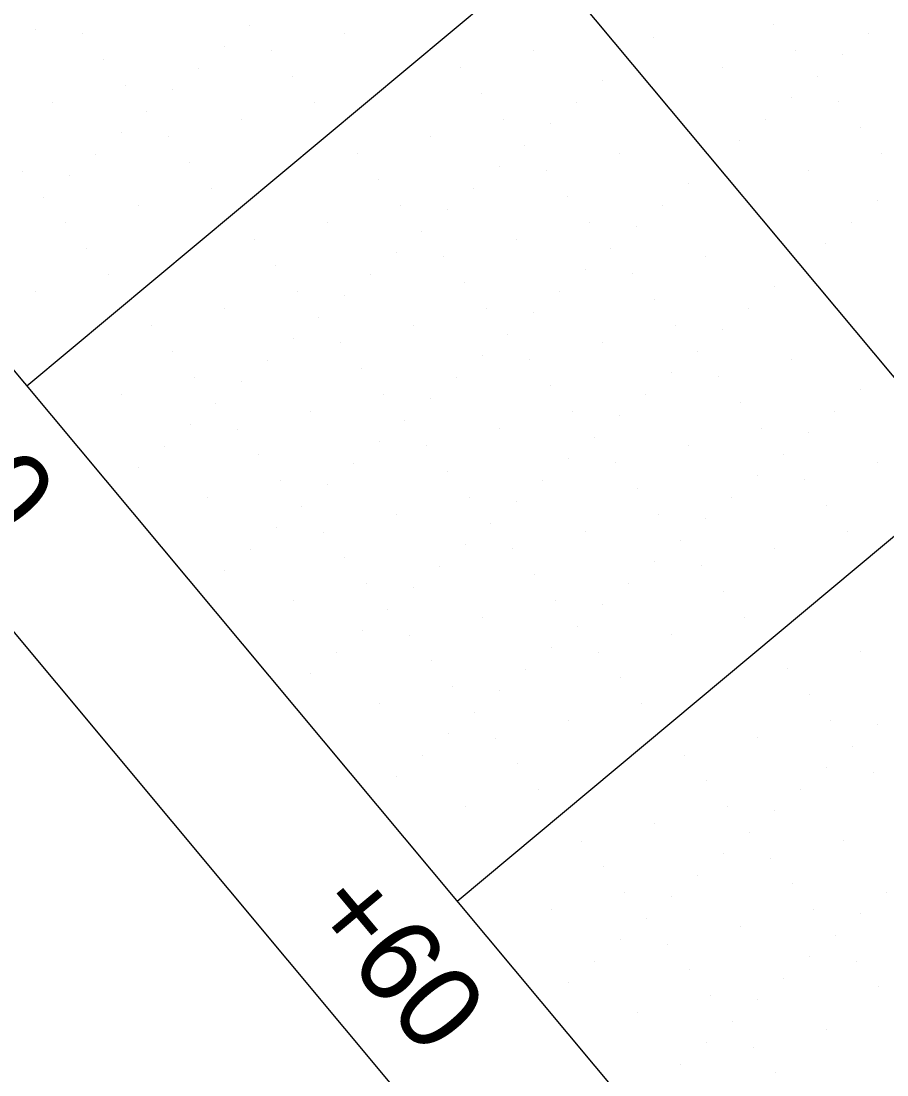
# Model space of a CAD drawing. Extents: x 2042995 to 2043795, y 305365 to 306249.
# Drawn here: x 2043194.69 to 2043220.5, y 305730.9 to 305762.3 of the extents above; entities that cross this region are included whole.
import ezdxf

# ---------------------------------------------------------------- set-up
doc = ezdxf.new("R2010")
doc.units = 0
for name, color, linetype in [('BR_BORDER LINES', 7, 'Continuous'), ('BR_CONCRETE', 7, 'Continuous'), ('BR_GRID DOTS', 7, 'Continuous'), ('BR_GRID LINES', 7, 'Continuous'), ('BR_TEXT', 7, 'Continuous')]:
    doc.layers.add(name, color=color, linetype=linetype)

msp = doc.modelspace()

# ---------------------------------------------------------------- linework, layer by layer
at = {"layer": 'BR_BORDER LINES'}
for p, q in [((2043026.498, 305945.211), (2043458.121, 305428.416)), ((2043041.019, 305935.624), (2043355.122, 305559.54))]:
    msp.add_line(p, q, dxfattribs=at)
at = {"layer": 'BR_CONCRETE'}
msp.add_spline([(2043139.109, 306017.548), (2043148.199, 306007.16), (2043160.233, 305993.368), (2043172.245, 305979.557), (2043184.234, 305965.727), (2043196.201, 305951.879), (2043208.145, 305938.012), (2043220.067, 305924.126), (2043231.966, 305910.221), (2043243.843, 305896.297), (2043255.698, 305882.355), (2043267.529, 305868.394), (2043279.339, 305854.414), (2043291.126, 305840.415), (2043302.89, 305826.398), (2043314.632, 305812.361), (2043326.352, 305798.306), (2043338.049, 305784.233), (2043349.724, 305770.14), (2043361.376, 305756.029), (2043373.005, 305741.899), (2043384.613, 305727.75), (2043396.197, 305713.582), (2043407.76, 305699.396), (2043419.299, 305685.191), (2043430.817, 305670.967), (2043442.311, 305656.724), (2043453.784, 305642.463), (2043465.234, 305628.182), (2043476.661, 305613.883), (2043488.066, 305599.566), (2043499.448, 305585.229), (2043510.808, 305570.874), (2043522.146, 305556.5), (2043533.461, 305542.107), (2043544.753, 305527.695), (2043547.219, 305524.543)], degree=3, dxfattribs=at)
at = {"layer": 'BR_GRID DOTS'}
for p, q in [((2043201.511, 305762.182), (2043201.511, 305762.182)), ((2043217.132, 305762.199), (2043217.132, 305762.199)), ((2043195.11, 305762.047), (2043195.11, 305762.047)), ((2043196.518, 305761.92), (2043196.518, 305761.92)), ((2043204.328, 305761.929), (2043204.328, 305761.929)), ((2043213.547, 305761.811), (2043213.547, 305761.811)), ((2043219.949, 305761.946), (2043219.949, 305761.946)), ((2043200.744, 305761.541), (2043200.744, 305761.541)), ((2043202.152, 305761.414), (2043202.152, 305761.414)), ((2043209.963, 305761.423), (2043209.963, 305761.423)), ((2043212.78, 305761.17), (2043212.78, 305761.17)), ((2043217.773, 305761.432), (2043217.773, 305761.432)), ((2043219.181, 305761.305), (2043219.181, 305761.305)), ((2043197.159, 305761.153), (2043197.159, 305761.153)), ((2043199.976, 305760.9), (2043199.976, 305760.9)), ((2043207.787, 305760.909), (2043207.787, 305760.909)), ((2043215.597, 305760.917), (2043215.597, 305760.917)), ((2043202.793, 305760.647), (2043202.793, 305760.647)), ((2043212.012, 305760.529), (2043212.012, 305760.529)), ((2043218.414, 305760.664), (2043218.414, 305760.664)), ((2043197.8, 305760.385), (2043197.8, 305760.385)), ((2043199.209, 305760.259), (2043199.209, 305760.259)), ((2043208.428, 305760.141), (2043208.428, 305760.141)), ((2043217.646, 305760.023), (2043217.646, 305760.023)), ((2043195.624, 305759.871), (2043195.624, 305759.871)), ((2043198.441, 305759.618), (2043198.441, 305759.618)), ((2043203.434, 305759.879), (2043203.434, 305759.879)), ((2043211.245, 305759.888), (2043211.245, 305759.888)), ((2043219.055, 305759.897), (2043219.055, 305759.897)), ((2043201.258, 305759.365), (2043201.258, 305759.365)), ((2043209.069, 305759.373), (2043209.069, 305759.373)), ((2043216.879, 305759.382), (2043216.879, 305759.382)), ((2043197.674, 305758.977), (2043197.674, 305758.977)), ((2043210.477, 305759.247), (2043210.477, 305759.247)), ((2043219.696, 305759.129), (2043219.696, 305759.129)), ((2043199.082, 305758.85), (2043199.082, 305758.85)), ((2043206.893, 305758.859), (2043206.893, 305758.859)), ((2043216.111, 305758.741), (2043216.111, 305758.741)), ((2043196.906, 305758.336), (2043196.906, 305758.336)), ((2043204.717, 305758.344), (2043204.717, 305758.344)), ((2043209.71, 305758.606), (2043209.71, 305758.606)), ((2043212.527, 305758.353), (2043212.527, 305758.353)), ((2043220.337, 305758.362), (2043220.337, 305758.362)), ((2043199.723, 305758.083), (2043199.723, 305758.083)), ((2043215.344, 305758.1), (2043215.344, 305758.1)), ((2043194.73, 305757.821), (2043194.73, 305757.821)), ((2043208.942, 305757.965), (2043208.942, 305757.965)), ((2043210.351, 305757.838), (2043210.351, 305757.838)), ((2043218.161, 305757.847), (2043218.161, 305757.847)), ((2043196.139, 305757.695), (2043196.139, 305757.695)), ((2043205.358, 305757.577), (2043205.358, 305757.577)), ((2043214.576, 305757.459), (2043214.576, 305757.459)), ((2043200.364, 305757.315), (2043200.364, 305757.315)), ((2043208.175, 305757.324), (2043208.175, 305757.324)), ((2043210.992, 305757.071), (2043210.992, 305757.071)), ((2043195.371, 305757.054), (2043195.371, 305757.054)), ((2043198.188, 305756.801), (2043198.188, 305756.801)), ((2043205.999, 305756.809), (2043205.999, 305756.809)), ((2043213.809, 305756.818), (2043213.809, 305756.818)), ((2043220.211, 305756.953), (2043220.211, 305756.953)), ((2043207.407, 305756.683), (2043207.407, 305756.683)), ((2043196.012, 305756.286), (2043196.012, 305756.286)), ((2043203.823, 305756.295), (2043203.823, 305756.295)), ((2043211.633, 305756.303), (2043211.633, 305756.303)), ((2043213.041, 305756.177), (2043213.041, 305756.177)), ((2043219.443, 305756.312), (2043219.443, 305756.312)), ((2043206.64, 305756.042), (2043206.64, 305756.042)), ((2043196.653, 305755.519), (2043196.653, 305755.519)), ((2043201.646, 305755.78), (2043201.646, 305755.78)), ((2043209.457, 305755.789), (2043209.457, 305755.789)), ((2043212.274, 305755.536), (2043212.274, 305755.536)), ((2043218.675, 305755.671), (2043218.675, 305755.671)), ((2043205.872, 305755.401), (2043205.872, 305755.401)), ((2043207.281, 305755.274), (2043207.281, 305755.274)), ((2043215.091, 305755.283), (2043215.091, 305755.283)), ((2043202.287, 305755.013), (2043202.287, 305755.013)), ((2043211.506, 305754.895), (2043211.506, 305754.895)), ((2043217.908, 305755.03), (2043217.908, 305755.03)), ((2043197.294, 305754.751), (2043197.294, 305754.751)), ((2043205.105, 305754.76), (2043205.105, 305754.76)), ((2043212.915, 305754.768), (2043212.915, 305754.768)), ((2043202.929, 305754.245), (2043202.929, 305754.245)), ((2043207.922, 305754.507), (2043207.922, 305754.507)), ((2043210.739, 305754.254), (2043210.739, 305754.254)), ((2043217.14, 305754.389), (2043217.14, 305754.389)), ((2043195.118, 305754.237), (2043195.118, 305754.237)), ((2043204.337, 305754.119), (2043204.337, 305754.119)), ((2043213.556, 305754.001), (2043213.556, 305754.001)), ((2043200.752, 305753.731), (2043200.752, 305753.731)), ((2043208.563, 305753.739), (2043208.563, 305753.739)), ((2043216.373, 305753.748), (2043216.373, 305753.748)), ((2043203.57, 305753.478), (2043203.57, 305753.478)), ((2043209.971, 305753.613), (2043209.971, 305753.613)), ((2043198.576, 305753.216), (2043198.576, 305753.216)), ((2043206.387, 305753.225), (2043206.387, 305753.225)), ((2043214.197, 305753.233), (2043214.197, 305753.233)), ((2043215.605, 305753.107), (2043215.605, 305753.107)), ((2043202.802, 305752.837), (2043202.802, 305752.837)), ((2043204.211, 305752.71), (2043204.211, 305752.71)), ((2043209.204, 305752.972), (2043209.204, 305752.972)), ((2043212.021, 305752.719), (2043212.021, 305752.719)), ((2043199.217, 305752.449), (2043199.217, 305752.449)), ((2043214.838, 305752.466), (2043214.838, 305752.466)), ((2043202.034, 305752.196), (2043202.034, 305752.196)), ((2043208.436, 305752.331), (2043208.436, 305752.331)), ((2043209.845, 305752.204), (2043209.845, 305752.204)), ((2043217.655, 305752.213), (2043217.655, 305752.213)), ((2043204.852, 305751.943), (2043204.852, 305751.943)), ((2043214.07, 305751.825), (2043214.07, 305751.825)), ((2043220.472, 305751.96), (2043220.472, 305751.96)), ((2043199.858, 305751.681), (2043199.858, 305751.681)), ((2043201.267, 305751.555), (2043201.267, 305751.555)), ((2043207.669, 305751.69), (2043207.669, 305751.69)), ((2043210.486, 305751.437), (2043210.486, 305751.437)), ((2043215.479, 305751.698), (2043215.479, 305751.698)), ((2043197.682, 305751.167), (2043197.682, 305751.167)), ((2043205.493, 305751.175), (2043205.493, 305751.175)), ((2043213.303, 305751.184), (2043213.303, 305751.184)), ((2043219.705, 305751.319), (2043219.705, 305751.319)), ((2043200.499, 305750.914), (2043200.499, 305750.914)), ((2043206.901, 305751.049), (2043206.901, 305751.049)), ((2043216.12, 305750.931), (2043216.12, 305750.931)), ((2043203.317, 305750.661), (2043203.317, 305750.661)), ((2043211.127, 305750.669), (2043211.127, 305750.669)), ((2043212.535, 305750.543), (2043212.535, 305750.543)), ((2043218.937, 305750.678), (2043218.937, 305750.678)), ((2043199.732, 305750.273), (2043199.732, 305750.273)), ((2043206.134, 305750.408), (2043206.134, 305750.408)), ((2043216.761, 305750.163), (2043216.761, 305750.163)), ((2043201.14, 305750.146), (2043201.14, 305750.146)), ((2043208.951, 305750.155), (2043208.951, 305750.155)), ((2043211.768, 305749.902), (2043211.768, 305749.902)), ((2043218.17, 305750.037), (2043218.17, 305750.037)), ((2043198.964, 305749.632), (2043198.964, 305749.632)), ((2043205.366, 305749.767), (2043205.366, 305749.767)), ((2043206.775, 305749.64), (2043206.775, 305749.64)), ((2043214.585, 305749.649), (2043214.585, 305749.649)), ((2043201.782, 305749.379), (2043201.782, 305749.379)), ((2043211, 305749.261), (2043211, 305749.261)), ((2043217.402, 305749.396), (2043217.402, 305749.396)), ((2043198.197, 305748.991), (2043198.197, 305748.991)), ((2043204.599, 305749.126), (2043204.599, 305749.126)), ((2043212.409, 305749.134), (2043212.409, 305749.134)), ((2043220.219, 305749.143), (2043220.219, 305749.143)), ((2043202.423, 305748.611), (2043202.423, 305748.611)), ((2043207.416, 305748.873), (2043207.416, 305748.873)), ((2043210.233, 305748.62), (2043210.233, 305748.62)), ((2043216.634, 305748.755), (2043216.634, 305748.755)), ((2043218.043, 305748.628), (2043218.043, 305748.628)), ((2043203.831, 305748.485), (2043203.831, 305748.485)), ((2043213.05, 305748.367), (2043213.05, 305748.367)), ((2043200.246, 305748.097), (2043200.246, 305748.097)), ((2043208.057, 305748.105), (2043208.057, 305748.105)), ((2043209.465, 305747.979), (2043209.465, 305747.979)), ((2043215.867, 305748.114), (2043215.867, 305748.114)), ((2043203.064, 305747.844), (2043203.064, 305747.844)), ((2043218.684, 305747.861), (2043218.684, 305747.861)), ((2043205.881, 305747.591), (2043205.881, 305747.591)), ((2043208.698, 305747.338), (2043208.698, 305747.338)), ((2043213.691, 305747.599), (2043213.691, 305747.599)), ((2043215.099, 305747.473), (2043215.099, 305747.473)), ((2043202.296, 305747.203), (2043202.296, 305747.203)), ((2043203.705, 305747.076), (2043203.705, 305747.076)), ((2043211.515, 305747.085), (2043211.515, 305747.085)), ((2043219.325, 305747.093), (2043219.325, 305747.093)), ((2043214.332, 305746.832), (2043214.332, 305746.832)), ((2043201.529, 305746.562), (2043201.529, 305746.562)), ((2043207.93, 305746.697), (2043207.93, 305746.697)), ((2043209.339, 305746.57), (2043209.339, 305746.57)), ((2043217.149, 305746.579), (2043217.149, 305746.579)), ((2043204.346, 305746.309), (2043204.346, 305746.309)), ((2043213.564, 305746.191), (2043213.564, 305746.191)), ((2043200.761, 305745.92), (2043200.761, 305745.92)), ((2043207.163, 305746.056), (2043207.163, 305746.056)), ((2043209.98, 305745.803), (2043209.98, 305745.803)), ((2043214.973, 305746.064), (2043214.973, 305746.064)), ((2043204.987, 305745.541), (2043204.987, 305745.541)), ((2043212.797, 305745.55), (2043212.797, 305745.55)), ((2043206.395, 305745.415), (2043206.395, 305745.415)), ((2043215.614, 305745.297), (2043215.614, 305745.297)), ((2043202.811, 305745.026), (2043202.811, 305745.026)), ((2043210.621, 305745.035), (2043210.621, 305745.035)), ((2043212.029, 305744.909), (2043212.029, 305744.909)), ((2043205.628, 305744.773), (2043205.628, 305744.773)), ((2043208.445, 305744.521), (2043208.445, 305744.521)), ((2043216.255, 305744.529), (2043216.255, 305744.529)), ((2043211.262, 305744.268), (2043211.262, 305744.268)), ((2043204.86, 305744.132), (2043204.86, 305744.132)), ((2043206.269, 305744.006), (2043206.269, 305744.006)), ((2043214.079, 305744.015), (2043214.079, 305744.015)), ((2043210.494, 305743.626), (2043210.494, 305743.626)), ((2043204.093, 305743.491), (2043204.093, 305743.491)), ((2043211.903, 305743.5), (2043211.903, 305743.5)), ((2043219.713, 305743.509), (2043219.713, 305743.509)), ((2043206.91, 305743.238), (2043206.91, 305743.238)), ((2043209.727, 305742.985), (2043209.727, 305742.985)), ((2043217.537, 305742.994), (2043217.537, 305742.994)), ((2043203.325, 305742.85), (2043203.325, 305742.85)), ((2043212.544, 305742.732), (2043212.544, 305742.732)), ((2043207.551, 305742.471), (2043207.551, 305742.471)), ((2043208.959, 305742.344), (2043208.959, 305742.344)), ((2043218.178, 305742.227), (2043218.178, 305742.227)), ((2043205.375, 305741.956), (2043205.375, 305741.956)), ((2043208.192, 305741.703), (2043208.192, 305741.703)), ((2043213.185, 305741.965), (2043213.185, 305741.965)), ((2043211.009, 305741.45), (2043211.009, 305741.45)), ((2043218.819, 305741.459), (2043218.819, 305741.459)), ((2043207.424, 305741.062), (2043207.424, 305741.062)), ((2043220.228, 305741.332), (2043220.228, 305741.332)), ((2043208.833, 305740.936), (2043208.833, 305740.936)), ((2043216.643, 305740.944), (2043216.643, 305740.944)), ((2043214.467, 305740.43), (2043214.467, 305740.43)), ((2043219.46, 305740.691), (2043219.46, 305740.691)), ((2043206.657, 305740.421), (2043206.657, 305740.421)), ((2043209.474, 305740.168), (2043209.474, 305740.168)), ((2043218.693, 305740.05), (2043218.693, 305740.05)), ((2043220.101, 305739.924), (2043220.101, 305739.924)), ((2043205.889, 305739.78), (2043205.889, 305739.78)), ((2043215.108, 305739.662), (2043215.108, 305739.662)), ((2043210.115, 305739.401), (2043210.115, 305739.401)), ((2043217.925, 305739.409), (2043217.925, 305739.409)), ((2043207.939, 305738.886), (2043207.939, 305738.886)), ((2043215.749, 305738.895), (2043215.749, 305738.895)), ((2043217.158, 305738.768), (2043217.158, 305738.768)), ((2043213.573, 305738.38), (2043213.573, 305738.38)), ((2043216.39, 305738.127), (2043216.39, 305738.127)), ((2043211.397, 305737.866), (2043211.397, 305737.866)), ((2043219.207, 305737.874), (2043219.207, 305737.874)), ((2043215.623, 305737.486), (2043215.623, 305737.486)), ((2043217.031, 305737.36), (2043217.031, 305737.36)), ((2043212.038, 305737.098), (2043212.038, 305737.098)), ((2043214.855, 305736.845), (2043214.855, 305736.845)), ((2043217.672, 305736.592), (2043217.672, 305736.592)), ((2043212.679, 305736.331), (2043212.679, 305736.331)), ((2043214.087, 305736.204), (2043214.087, 305736.204)), ((2043220.489, 305736.339), (2043220.489, 305736.339)), ((2043210.503, 305735.816), (2043210.503, 305735.816)), ((2043218.313, 305735.825), (2043218.313, 305735.825)), ((2043213.32, 305735.563), (2043213.32, 305735.563)), ((2043219.722, 305735.698), (2043219.722, 305735.698)), ((2043216.137, 305735.31), (2043216.137, 305735.31)), ((2043212.552, 305734.922), (2043212.552, 305734.922)), ((2043213.961, 305734.796), (2043213.961, 305734.796)), ((2043218.954, 305735.057), (2043218.954, 305735.057)), ((2043211.785, 305734.281), (2043211.785, 305734.281)), ((2043218.187, 305734.416), (2043218.187, 305734.416)), ((2043219.595, 305734.29), (2043219.595, 305734.29)), ((2043214.602, 305734.028), (2043214.602, 305734.028)), ((2043211.017, 305733.64), (2043211.017, 305733.64)), ((2043217.419, 305733.775), (2043217.419, 305733.775)), ((2043220.236, 305733.522), (2043220.236, 305733.522)), ((2043215.243, 305733.261), (2043215.243, 305733.261)), ((2043216.652, 305733.134), (2043216.652, 305733.134)), ((2043213.067, 305732.746), (2043213.067, 305732.746)), ((2043215.884, 305732.493), (2043215.884, 305732.493)), ((2043218.701, 305732.24), (2043218.701, 305732.24)), ((2043215.117, 305731.852), (2043215.117, 305731.852)), ((2043216.525, 305731.726), (2043216.525, 305731.726)), ((2043214.349, 305731.211), (2043214.349, 305731.211)), ((2043217.166, 305730.958), (2043217.166, 305730.958))]:
    msp.add_line(p, q, dxfattribs=at)
at = {"layer": 'BR_GRID LINES'}
for p, q in [((2043348.369, 305879.625), (2043194.865, 305751.42)), ((2043361.19, 305864.274), (2043207.686, 305736.069)), ((2043133.293, 305856.342), (2043340.985, 305607.666))]:
    msp.add_line(p, q, dxfattribs=at)

# ---------------------------------------------------------------- texts
at = {"layer": 'BR_TEXT'}
for s, p in [('+40', (2043190.34, 305751.087)), ('+60', (2043203.161, 305735.737))]:
    msp.add_text(s, height=2.5, rotation=309.8684, dxfattribs=at).set_placement(p)

doc.saveas('drawing.dxf')
